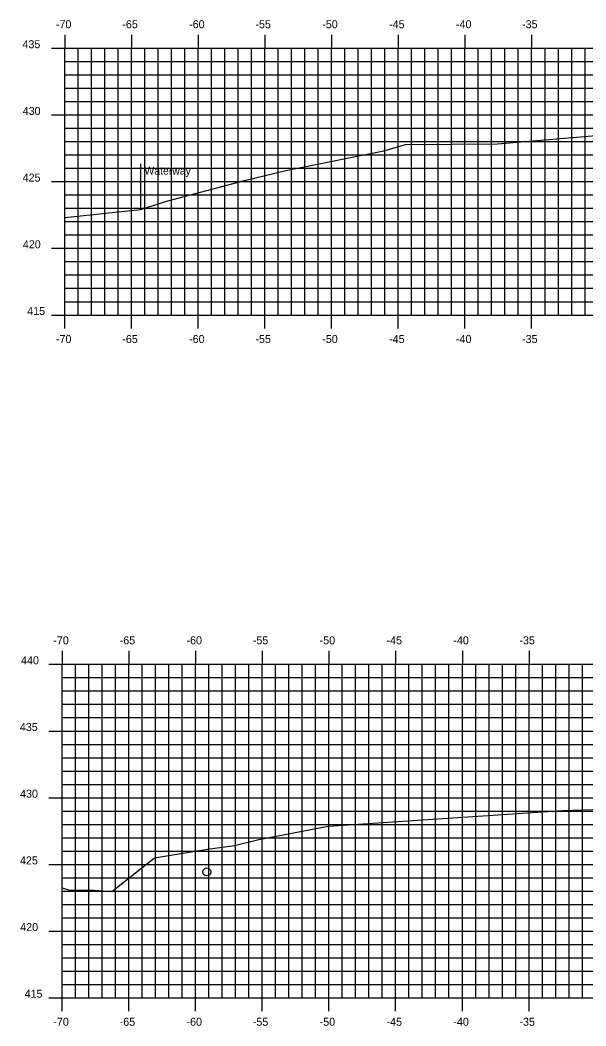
# Model space of a CAD drawing. Extents: x -161 to 764, y 111 to 210.
# Drawn here: x 337.2 to 379.7, y 122.9 to 198.4 of the extents above; entities that cross this region are included whole.
import ezdxf

# ---------------------------------------------------------------- set-up
doc = ezdxf.new("R2010")
doc.units = 0
for name, color, linetype in [('H_V ANNOTATION', 7, 'Continuous'), ('MAJOR', 7, 'Continuous'), ('MINOR', 7, 'Continuous'), ('S_Drainage_Invert', 7, 'Continuous'), ('S_Drainage_Waterway', 7, 'Continuous'), ('S_Roadway_Centerline', 7, 'Continuous')]:
    doc.layers.add(name, color=color, linetype=linetype)

msp = doc.modelspace()

# ---------------------------------------------------------------- linework, layer by layer
at = {"layer": 'MAJOR'}
for p, q in [((340.591, 197.249), (340.591, 196.247)), ((345.591, 197.249), (345.591, 196.247)), ((350.591, 197.249), (350.591, 196.247)), ((355.591, 197.249), (355.591, 196.247)), ((360.591, 197.249), (360.591, 196.247)), ((365.591, 197.249), (365.591, 196.247)), ((370.591, 197.249), (370.591, 196.247)), ((375.591, 197.249), (375.591, 196.247)), ((339.589, 196.247), (340.591, 196.247)), ((340.591, 196.247), (480.591, 196.247)), ((340.591, 176.247), (340.591, 196.247)), ((340.591, 176.247), (340.591, 196.247)), ((340.591, 196.247), (480.591, 196.247)), ((345.591, 176.247), (345.591, 196.247)), ((350.591, 176.247), (350.591, 196.247)), ((355.591, 176.247), (355.591, 196.247)), ((360.591, 176.247), (360.591, 196.247)), ((365.591, 176.247), (365.591, 196.247)), ((370.591, 176.247), (370.591, 196.247)), ((375.591, 176.247), (375.591, 196.247)), ((339.589, 191.247), (340.591, 191.247)), ((340.591, 191.247), (480.591, 191.247)), ((339.589, 186.247), (340.591, 186.247)), ((340.591, 186.247), (480.591, 186.247)), ((339.589, 181.247), (340.591, 181.247)), ((340.591, 181.247), (480.591, 181.247)), ((339.589, 176.247), (340.591, 176.247)), ((340.591, 176.247), (480.591, 176.247)), ((340.591, 176.247), (480.591, 176.247)), ((340.591, 175.245), (340.591, 176.247)), ((345.591, 175.245), (345.591, 176.247)), ((350.591, 175.245), (350.591, 176.247)), ((355.591, 175.245), (355.591, 176.247)), ((360.591, 175.245), (360.591, 176.247)), ((365.591, 175.245), (365.591, 176.247)), ((370.591, 175.245), (370.591, 176.247)), ((375.591, 175.245), (375.591, 176.247)), ((340.395, 151.06), (340.395, 150.058)), ((345.395, 151.06), (345.395, 150.058)), ((350.395, 151.06), (350.395, 150.058)), ((355.395, 151.06), (355.395, 150.058)), ((360.395, 151.06), (360.395, 150.058)), ((365.395, 151.06), (365.395, 150.058)), ((370.395, 151.06), (370.395, 150.058)), ((375.395, 151.06), (375.395, 150.058)), ((339.393, 150.058), (340.395, 150.058)), ((340.395, 150.058), (480.395, 150.058)), ((340.395, 125.058), (340.395, 150.058)), ((340.395, 125.058), (340.395, 150.058)), ((340.395, 150.058), (480.395, 150.058)), ((345.395, 125.058), (345.395, 150.058)), ((350.395, 125.058), (350.395, 150.058)), ((355.395, 125.058), (355.395, 150.058)), ((360.395, 125.058), (360.395, 150.058)), ((365.395, 125.058), (365.395, 150.058)), ((370.395, 125.058), (370.395, 150.058)), ((375.395, 125.058), (375.395, 150.058)), ((339.393, 145.058), (340.395, 145.058)), ((340.395, 145.058), (480.395, 145.058)), ((339.393, 140.058), (340.395, 140.058)), ((340.395, 140.058), (480.395, 140.058)), ((339.393, 135.058), (340.395, 135.058)), ((340.395, 135.058), (480.395, 135.058)), ((339.393, 130.058), (340.395, 130.058)), ((340.395, 130.058), (480.395, 130.058)), ((339.393, 125.058), (340.395, 125.058)), ((340.395, 125.058), (480.395, 125.058)), ((340.395, 125.058), (480.395, 125.058)), ((340.395, 124.056), (340.395, 125.058)), ((345.395, 124.056), (345.395, 125.058)), ((350.395, 124.056), (350.395, 125.058)), ((355.395, 124.056), (355.395, 125.058)), ((360.395, 124.056), (360.395, 125.058)), ((365.395, 124.056), (365.395, 125.058)), ((370.395, 124.056), (370.395, 125.058)), ((375.395, 124.056), (375.395, 125.058))]:
    msp.add_line(p, q, dxfattribs=at)
at = {"layer": 'MINOR'}
for p, q in [((341.591, 176.247), (341.591, 196.247)), ((342.591, 176.247), (342.591, 196.247)), ((343.591, 176.247), (343.591, 196.247)), ((344.591, 176.247), (344.591, 196.247)), ((346.591, 176.247), (346.591, 196.247)), ((347.591, 176.247), (347.591, 196.247)), ((348.591, 176.247), (348.591, 196.247)), ((349.591, 176.247), (349.591, 196.247)), ((351.591, 176.247), (351.591, 196.247)), ((352.591, 176.247), (352.591, 196.247)), ((353.591, 176.247), (353.591, 196.247)), ((354.591, 176.247), (354.591, 196.247)), ((356.591, 176.247), (356.591, 196.247)), ((357.591, 176.247), (357.591, 196.247)), ((358.591, 176.247), (358.591, 196.247)), ((359.591, 176.247), (359.591, 196.247)), ((361.591, 176.247), (361.591, 196.247)), ((362.591, 176.247), (362.591, 196.247)), ((363.591, 176.247), (363.591, 196.247)), ((364.591, 176.247), (364.591, 196.247)), ((366.591, 176.247), (366.591, 196.247)), ((367.591, 176.247), (367.591, 196.247)), ((368.591, 176.247), (368.591, 196.247)), ((369.591, 176.247), (369.591, 196.247)), ((371.591, 176.247), (371.591, 196.247)), ((372.591, 176.247), (372.591, 196.247)), ((373.591, 176.247), (373.591, 196.247)), ((374.591, 176.247), (374.591, 196.247)), ((376.591, 176.247), (376.591, 196.247)), ((377.591, 176.247), (377.591, 196.247)), ((378.591, 176.247), (378.591, 196.247)), ((379.591, 176.247), (379.591, 196.247)), ((340.591, 195.247), (480.591, 195.247)), ((340.591, 195.247), (341.593, 195.247)), ((340.591, 194.247), (480.591, 194.247)), ((340.591, 194.247), (341.593, 194.247)), ((340.591, 193.247), (480.591, 193.247)), ((340.591, 193.247), (341.593, 193.247)), ((340.591, 192.247), (480.591, 192.247)), ((340.591, 192.247), (341.593, 192.247)), ((340.591, 190.247), (480.591, 190.247)), ((340.591, 190.247), (341.593, 190.247)), ((340.591, 189.247), (480.591, 189.247)), ((340.591, 189.247), (341.593, 189.247)), ((340.591, 188.247), (480.591, 188.247)), ((340.591, 188.247), (341.593, 188.247)), ((340.591, 187.247), (480.591, 187.247)), ((340.591, 187.247), (341.593, 187.247)), ((340.591, 185.247), (480.591, 185.247)), ((340.591, 185.247), (341.593, 185.247)), ((340.591, 184.247), (480.591, 184.247)), ((340.591, 184.247), (341.593, 184.247)), ((340.591, 183.247), (480.591, 183.247)), ((340.591, 183.247), (341.593, 183.247)), ((340.591, 182.247), (480.591, 182.247)), ((340.591, 182.247), (341.593, 182.247)), ((340.591, 180.247), (480.591, 180.247)), ((340.591, 180.247), (341.593, 180.247)), ((340.591, 179.247), (480.591, 179.247)), ((340.591, 179.247), (341.593, 179.247)), ((340.591, 178.247), (480.591, 178.247)), ((340.591, 178.247), (341.593, 178.247)), ((340.591, 177.247), (480.591, 177.247)), ((340.591, 177.247), (341.593, 177.247)), ((341.395, 125.058), (341.395, 150.058)), ((342.395, 125.058), (342.395, 150.058)), ((343.395, 125.058), (343.395, 150.058)), ((344.395, 125.058), (344.395, 150.058)), ((346.395, 125.058), (346.395, 150.058)), ((347.395, 125.058), (347.395, 150.058)), ((348.395, 125.058), (348.395, 150.058)), ((349.395, 125.058), (349.395, 150.058)), ((351.395, 125.058), (351.395, 150.058)), ((352.395, 125.058), (352.395, 150.058)), ((353.395, 125.058), (353.395, 150.058)), ((354.395, 125.058), (354.395, 150.058)), ((356.395, 125.058), (356.395, 150.058)), ((357.395, 125.058), (357.395, 150.058)), ((358.395, 125.058), (358.395, 150.058)), ((359.395, 125.058), (359.395, 150.058)), ((361.395, 125.058), (361.395, 150.058)), ((362.395, 125.058), (362.395, 150.058)), ((363.395, 125.058), (363.395, 150.058)), ((364.395, 125.058), (364.395, 150.058)), ((366.395, 125.058), (366.395, 150.058)), ((367.395, 125.058), (367.395, 150.058)), ((368.395, 125.058), (368.395, 150.058)), ((369.395, 125.058), (369.395, 150.058)), ((371.395, 125.058), (371.395, 150.058)), ((372.395, 125.058), (372.395, 150.058)), ((373.395, 125.058), (373.395, 150.058)), ((374.395, 125.058), (374.395, 150.058)), ((376.395, 125.058), (376.395, 150.058)), ((377.395, 125.058), (377.395, 150.058)), ((378.395, 125.058), (378.395, 150.058)), ((379.395, 125.058), (379.395, 150.058)), ((340.395, 149.058), (480.395, 149.058)), ((340.395, 149.058), (341.397, 149.058)), ((340.395, 148.058), (480.395, 148.058)), ((340.395, 148.058), (341.397, 148.058)), ((340.395, 147.058), (480.395, 147.058)), ((340.395, 147.058), (341.397, 147.058)), ((340.395, 146.058), (480.395, 146.058)), ((340.395, 146.058), (341.397, 146.058)), ((340.395, 144.058), (480.395, 144.058)), ((340.395, 144.058), (341.397, 144.058)), ((340.395, 143.058), (480.395, 143.058)), ((340.395, 143.058), (341.397, 143.058)), ((340.395, 142.058), (480.395, 142.058)), ((340.395, 142.058), (341.397, 142.058)), ((340.395, 141.058), (480.395, 141.058)), ((340.395, 141.058), (341.397, 141.058)), ((340.395, 139.058), (480.395, 139.058)), ((340.395, 139.058), (341.397, 139.058)), ((340.395, 138.058), (480.395, 138.058)), ((340.395, 138.058), (341.397, 138.058)), ((340.395, 137.058), (480.395, 137.058)), ((340.395, 137.058), (341.397, 137.058)), ((340.395, 136.058), (480.395, 136.058)), ((340.395, 136.058), (341.397, 136.058)), ((340.395, 134.058), (480.395, 134.058)), ((340.395, 134.058), (341.397, 134.058)), ((340.395, 133.058), (480.395, 133.058)), ((340.395, 133.058), (341.397, 133.058)), ((340.395, 132.058), (480.395, 132.058)), ((340.395, 132.058), (341.397, 132.058)), ((340.395, 131.058), (480.395, 131.058)), ((340.395, 131.058), (341.397, 131.058)), ((340.395, 129.058), (480.395, 129.058)), ((340.395, 129.058), (341.397, 129.058)), ((340.395, 128.058), (480.395, 128.058)), ((340.395, 128.058), (341.397, 128.058)), ((340.395, 127.058), (480.395, 127.058)), ((340.395, 127.058), (341.397, 127.058)), ((340.395, 126.058), (480.395, 126.058)), ((340.395, 126.058), (341.397, 126.058))]:
    msp.add_line(p, q, dxfattribs=at)
at = {"layer": 'S_Drainage_Invert'}
msp.add_circle((351.244, 134.496), 0.3, dxfattribs=at)
at = {"layer": 'S_Drainage_Waterway'}
msp.add_line((346.27, 187.587), (346.27, 184.146), dxfattribs=at)
at = {"layer": 'S_Roadway_Centerline'}
for points in [[(340.591, 183.558), (346.27, 184.146), (348.315, 184.806), (354.074, 186.337), (357.168, 187.075), (364.507, 188.564), (366.124, 189.037), (373.039, 189.084), (380.424, 189.717), (384.106, 189.757), (390.092, 189.37), (397.718, 189.529), (407.599, 189.997), (414.618, 189.716), (422.879, 189.785), (430.793, 190.018)], [(340.395, 133.296), (340.882, 133.162), (342.829, 133.127), (344.117, 133.013), (346.843, 135.18), (347.307, 135.532), (347.479, 135.579), (351.296, 136.205), (353.326, 136.466), (355.138, 136.92), (360.341, 137.916), (377.913, 139.096), (380.185, 139.185), (381.124, 139.189), (381.917, 139.256), (386.308, 139.297), (388.872, 139.316), (405.982, 139.809), (415.26, 140.13), (422.294, 140.074), (433.65, 140.066)]]:
    msp.add_lwpolyline(points, dxfattribs=at)

# ---------------------------------------------------------------- texts
at = {"layer": 'H_V ANNOTATION'}
for s, p in [('-70', (339.933, 197.747)), ('-65', (344.909, 197.747)), ('-60', (349.917, 197.747)), ('-55', (354.887, 197.747)), ('-50', (359.895, 197.747)), ('-45', (364.909, 197.747)), ('-40', (369.917, 197.747)), ('-35', (374.871, 197.747)), ('435', (337.427, 196.247)), ('430', (337.443, 191.247)), ('425', (337.437, 186.247)), ('420', (337.453, 181.247)), ('415', (337.78, 176.247)), ('-70', (339.933, 174.147)), ('-65', (344.909, 174.147)), ('-60', (349.917, 174.147)), ('-55', (354.887, 174.147)), ('-50', (359.895, 174.147)), ('-45', (364.909, 174.147)), ('-40', (369.917, 174.147)), ('-35', (374.871, 174.147)), ('-70', (339.737, 151.558)), ('-65', (344.713, 151.558)), ('-60', (349.721, 151.558)), ('-55', (354.691, 151.558)), ('-50', (359.699, 151.558)), ('-45', (364.713, 151.558)), ('-40', (369.721, 151.558)), ('-35', (374.675, 151.558)), ('440', (337.322, 150.058)), ('435', (337.231, 145.058)), ('430', (337.247, 140.058)), ('425', (337.241, 135.058)), ('420', (337.257, 130.058)), ('415', (337.584, 125.058)), ('-70', (339.737, 122.958)), ('-65', (344.713, 122.958)), ('-60', (349.721, 122.958)), ('-55', (354.691, 122.958)), ('-50', (359.699, 122.958)), ('-45', (364.713, 122.958)), ('-40', (369.721, 122.958)), ('-35', (374.675, 122.958))]:
    msp.add_text(s, height=0.6, rotation=360, dxfattribs=at).set_placement(p)
at = {"layer": 'MAJOR'}
for p in [(340.587, 176.247), (340.391, 125.058)]:
    msp.add_text('-', height=1.5248952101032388e-17, rotation=53.1301, dxfattribs=at).set_placement(p)
at = {"layer": 'S_Drainage_Waterway'}
msp.add_text('Waterway', height=0.585, rotation=360, dxfattribs=at).set_placement((346.568, 186.775))

doc.saveas('drawing.dxf')
